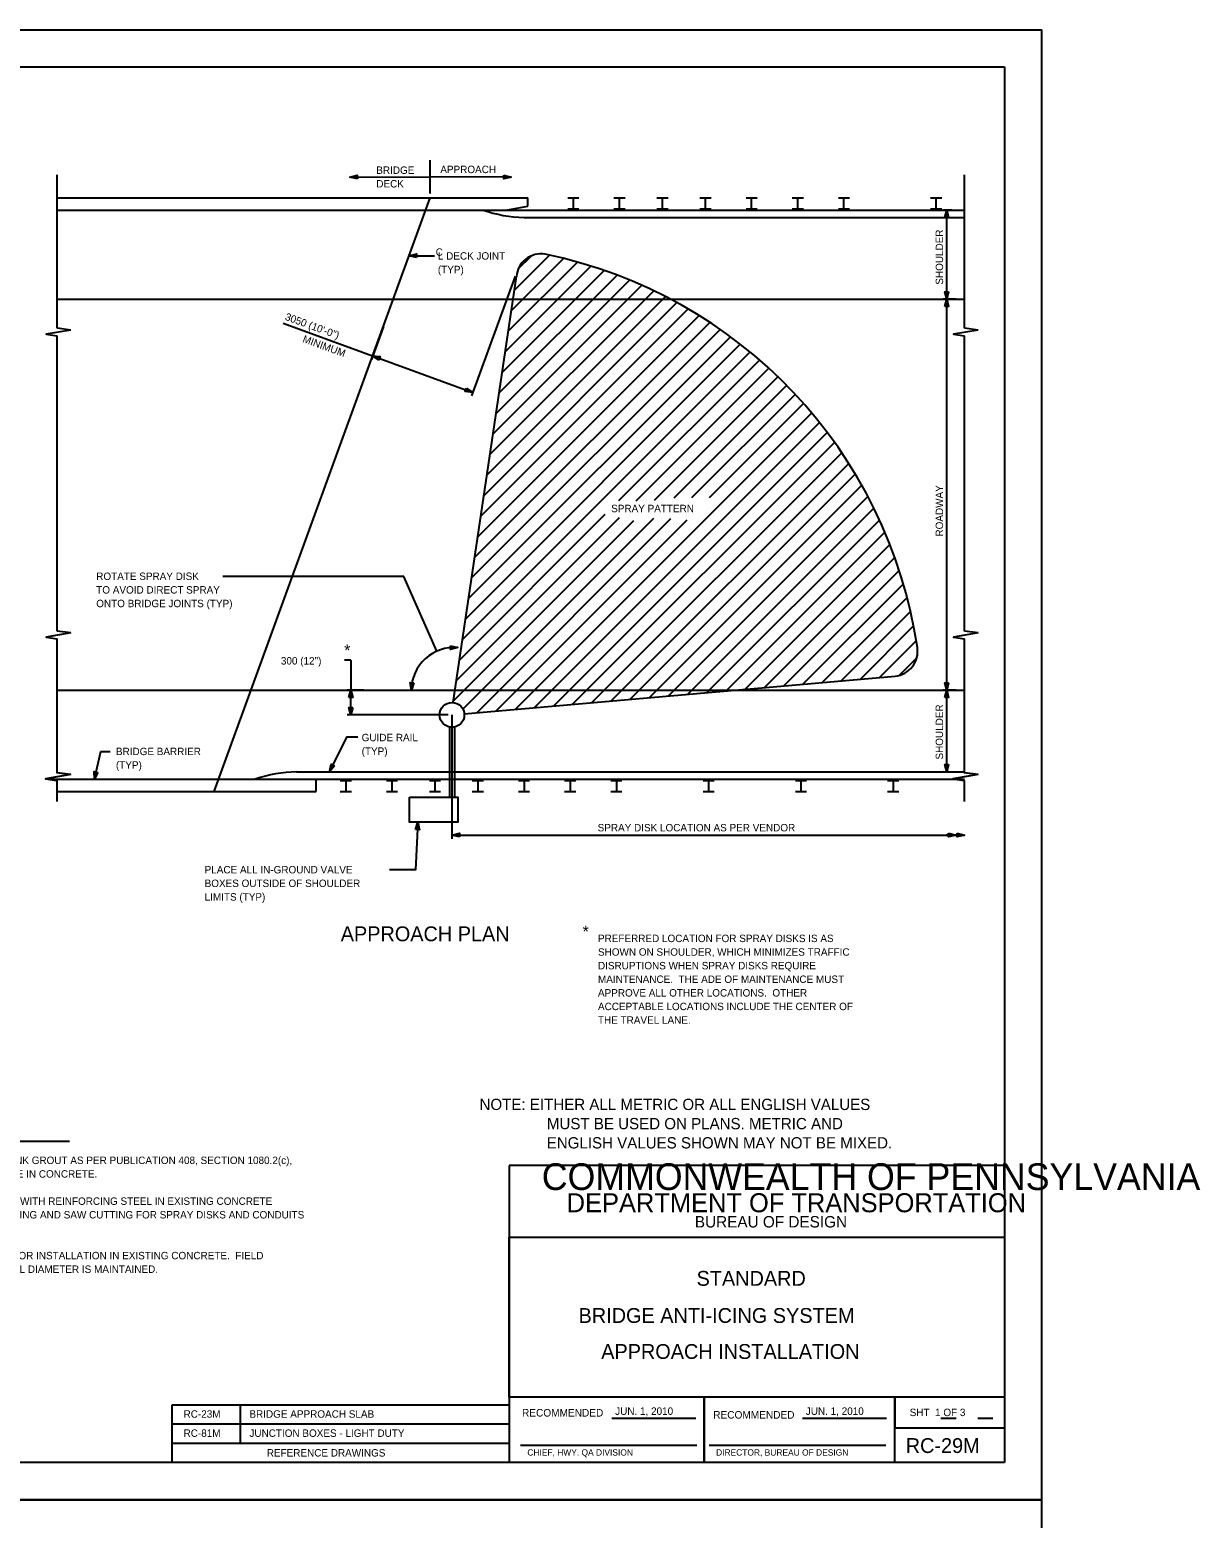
# Model space of a CAD drawing. Extents: x 3239 to 4230, y -4276 to -2494.
# Drawn here: x 3671 to 4144, y -3096 to -2494 of the extents above; entities that cross this region are included whole.
import ezdxf

# ---------------------------------------------------------------- set-up
doc = ezdxf.new("R2010")
doc.units = 0
for name, color, linetype in [('1', 7, 'Continuous'), ('2', 7, 'Continuous'), ('40', 7, 'Continuous'), ('PLT-BNDY', 7, 'Continuous')]:
    doc.layers.add(name, color=color, linetype=linetype)

msp = doc.modelspace()

# ---------------------------------------------------------------- linework, layer by layer
at = {"layer": '1'}
for p, q in [((4065.03, -2953.29), (3865.03, -2953.29)), ((3865.03, -2953.29), (3865.03, -3073.29)), ((3865.03, -3046.93), (3865.03, -2982.25)), ((3865.03, -2982.25), (4065.03, -2982.25)), ((4065.03, -3046.93), (3865.03, -3046.93)), ((3943.83, -3073.29), (3943.83, -3046.93)), ((3943.83, -3046.93), (3943.83, -3073.29)), ((4020.83, -3073.29), (4020.83, -3046.93)), ((4020.83, -3046.93), (4020.83, -3059.25)), ((3906.49, -3055.3), (3940.38, -3055.3)), ((3983.49, -3055.3), (4017.36, -3055.3)), ((4039.41, -3055.33), (4045.55, -3055.33)), ((4054.27, -3055.33), (4060.43, -3055.33)), ((4020.83, -3059.25), (4065.03, -3059.25)), ((3869.59, -3066.21), (3940.84, -3066.21)), ((3945.76, -3066.21), (4017.1, -3066.21))]:
    msp.add_line(p, q, dxfattribs=at)
at = {"layer": '2'}
for p, q in [((3279.03, -2509.29), (4065.03, -2509.29)), ((4065.03, -2509.29), (4065.03, -3073.29)), ((3833.14, -2560.5), (3833.14, -2547.02)), ((3682.42, -2614.94), (3682.42, -2552.89)), ((3800.66, -2553.82), (3833.14, -2553.71)), ((3865.82, -2553.82), (3833.14, -2553.71)), ((4048.93, -2614.94), (4048.93, -2552.89)), ((3682.42, -2562.14), (3872.54, -2562.14)), ((3745.78, -2802.15), (3833.14, -2562.14)), ((3872.54, -2565.54), (3872.54, -2562.14)), ((3888.7, -2562.15), (3893.2, -2562.15)), ((3890.95, -2566.65), (3890.95, -2562.15)), ((3907.34, -2562.15), (3911.84, -2562.15)), ((3909.59, -2566.65), (3909.59, -2562.15)), ((3924.7, -2562.15), (3929.2, -2562.15)), ((3926.95, -2566.65), (3926.95, -2562.15)), ((3942.06, -2562.15), (3946.56, -2562.15)), ((3944.31, -2566.65), (3944.31, -2562.15)), ((3960.7, -2562.15), (3965.2, -2562.15)), ((3962.95, -2566.65), (3962.95, -2562.15)), ((3979.34, -2562.15), (3983.84, -2562.15)), ((3981.59, -2566.65), (3981.59, -2562.15)), ((3997.98, -2562.15), (4002.48, -2562.15)), ((4000.23, -2566.65), (4000.23, -2562.15)), ((4035.26, -2562.15), (4039.76, -2562.15)), ((4037.51, -2566.65), (4037.51, -2562.15)), ((3682.42, -2567.14), (3863.67, -2567.14)), ((3863.67, -2567.14), (3872.54, -2565.54)), ((3863.67, -2567.14), (4048.93, -2567.14)), ((3888.7, -2566.65), (3893.2, -2566.65)), ((3907.34, -2566.65), (3911.84, -2566.65)), ((3924.7, -2566.65), (3929.2, -2566.65)), ((3942.06, -2566.65), (3946.56, -2566.65)), ((3960.7, -2566.65), (3965.2, -2566.65)), ((3979.34, -2566.65), (3983.84, -2566.65)), ((3997.98, -2566.65), (4002.48, -2566.65)), ((4035.26, -2566.65), (4039.76, -2566.65)), ((4043.79, -2567.14), (4040.28, -2567.14)), ((4041.78, -2603.14), (4041.78, -2567.14)), ((3871.04, -2570.14), (4048.93, -2570.14)), ((3824.59, -2585.63), (3834.84, -2585.63)), ((3867.1, -2599.52), (3881.26, -2585.36)), ((3868.83, -2590.71), (3873.82, -2585.72)), ((3862.16, -2632.74), (3903.37, -2591.53)), ((3863.39, -2624.43), (3898.03, -2589.8)), ((3864.63, -2616.13), (3892.59, -2588.16)), ((3865.86, -2607.82), (3886.99, -2586.7)), ((3842.32, -2766.17), (3867.92, -2593.97)), ((3867.46, -2593.9), (3849.79, -2642.25)), ((3858.45, -2657.66), (3918.6, -2597.51)), ((3859.69, -2649.35), (3913.62, -2595.42)), ((3860.92, -2641.05), (3908.56, -2593.41)), ((3682.42, -2603.14), (4048.93, -2603.14)), ((3855.98, -2674.27), (3928.15, -2602.1)), ((3857.22, -2665.96), (3923.41, -2599.77)), ((4045.53, -2603.14), (4040.28, -2603.14)), ((4041.78, -2761.15), (4041.78, -2603.14)), ((3852.28, -2699.19), (3941.73, -2609.74)), ((3853.51, -2690.88), (3937.28, -2607.11)), ((3854.75, -2682.58), (3932.78, -2604.54)), ((3687.93, -2615.62), (3682.42, -2614.94)), ((3773.68, -2612.84), (3850.3, -2640.84)), ((3814.17, -2614.24), (3809.34, -2627.47)), ((3849.81, -2715.8), (3950.24, -2615.37)), ((3851.04, -2707.49), (3946.01, -2612.52)), ((4054.44, -2615.62), (4048.93, -2614.94)), ((3682.42, -2737.37), (3682.42, -2617.96)), ((3847.34, -2732.41), (3958.37, -2621.38)), ((3848.57, -2724.11), (3954.35, -2618.32)), ((4048.93, -2737.37), (4048.93, -2617.96)), ((3846.1, -2740.72), (3962.32, -2624.5)), ((3909.32, -2684.57), (3966.13, -2627.76)), ((3916.26, -2684.7), (3969.89, -2631.07)), ((3923.66, -2684.38), (3973.52, -2634.51)), ((3931.65, -2683.46), (3977.08, -2638.02)), ((3938.85, -2683.33), (3980.55, -2641.63)), ((3945.99, -2683.26), (3983.9, -2645.34)), ((3867.4, -2768.91), (3987.21, -2649.11)), ((3875.15, -2768.24), (3990.36, -2653.03)), ((3882.9, -2767.56), (3993.47, -2656.99)), ((3890.65, -2766.88), (3996.44, -2661.09)), ((3898.4, -2766.2), (3999.34, -2665.26)), ((3906.15, -2765.52), (4002.15, -2669.52)), ((3913.9, -2764.85), (4004.83, -2673.91)), ((3921.65, -2764.17), (4007.46, -2678.36)), ((3929.4, -2763.49), (4009.92, -2682.96)), ((3937.15, -2762.81), (4012.32, -2687.64)), ((3842.4, -2765.64), (3915.4, -2692.63)), ((3843.63, -2757.33), (3909.58, -2691.39)), ((3844.87, -2749.02), (3903.81, -2690.08)), ((3846.26, -2768.84), (3923.46, -2691.65)), ((3851.91, -2770.27), (3930.33, -2691.84)), ((3859.65, -2769.59), (3936.95, -2692.3)), ((3944.89, -2762.13), (4014.6, -2692.43)), ((3952.64, -2761.46), (4016.75, -2697.35)), ((3960.39, -2760.78), (4018.82, -2702.35)), ((3968.14, -2760.1), (4020.73, -2707.51)), ((3822.44, -2715.2), (3749.29, -2715.2)), ((3835.78, -2745.36), (3822.44, -2715.2)), ((3975.89, -2759.42), (4022.53, -2712.78)), ((3983.64, -2758.74), (4024.23, -2718.15)), ((3991.39, -2758.07), (4025.73, -2723.72)), ((3999.14, -2757.39), (4027.12, -2729.4)), ((4006.89, -2756.71), (4028.39, -2735.2)), ((3687.93, -2738.05), (3682.42, -2737.37)), ((3682.42, -2794.58), (3682.42, -2740.39)), ((4014.64, -2756.03), (4029.43, -2741.23)), ((4054.44, -2738.05), (4048.93, -2737.37)), ((4048.93, -2794.58), (4048.93, -2740.39)), ((4022.57, -2755.17), (4029.67, -2748.07)), ((3801.05, -2749.05), (3798.47, -2749.05)), ((3801.05, -2749.05), (3801.05, -2761.15)), ((3801.05, -2771.15), (3801.05, -2760.8)), ((3846.86, -2770.71), (4020.9, -2755.49)), ((3682.42, -2761.15), (4048.93, -2761.15)), ((3806.29, -2761.15), (3799.55, -2761.15)), ((4045.55, -2761.15), (4040.28, -2761.15)), ((4041.78, -2794.15), (4041.78, -2761.15)), ((3840.38, -2771.15), (3799.55, -2771.15)), ((3841.88, -2771.15), (3841.88, -2821.23)), ((3840.88, -2776.05), (3840.88, -2804.44)), ((3842.88, -2776.05), (3842.88, -2804.44)), ((3687.62, -2795.26), (3682.11, -2794.58)), ((3687.93, -2795.26), (3682.42, -2794.58)), ((3779.09, -2794.15), (4048.93, -2794.15)), ((4040.43, -2794.15), (4040.28, -2794.15)), ((4054.13, -2795.26), (4048.62, -2794.58)), ((4054.44, -2795.26), (4048.93, -2794.58)), ((3679.34, -2797.15), (4048.93, -2797.15)), ((3682.42, -2806.14), (3682.42, -2797.6)), ((3682.42, -2802.15), (3787.01, -2802.15)), ((3787.01, -2802.15), (3787.01, -2797.15)), ((3796.76, -2797.63), (3801.26, -2797.63)), ((3796.76, -2802.13), (3801.26, -2802.13)), ((3799.01, -2797.63), (3799.01, -2802.13)), ((3815.4, -2797.63), (3819.9, -2797.63)), ((3815.4, -2802.13), (3819.9, -2802.13)), ((3817.65, -2797.63), (3817.65, -2802.13)), ((3832.76, -2797.63), (3837.26, -2797.63)), ((3832.76, -2802.13), (3837.26, -2802.13)), ((3835.01, -2797.63), (3835.01, -2802.13)), ((3850.11, -2797.63), (3854.61, -2797.63)), ((3850.11, -2802.13), (3854.61, -2802.13)), ((3852.36, -2797.63), (3852.36, -2802.13)), ((3868.76, -2797.63), (3873.26, -2797.63)), ((3868.76, -2802.13), (3873.26, -2802.13)), ((3871.01, -2797.63), (3871.01, -2802.13)), ((3887.4, -2797.63), (3891.9, -2797.63)), ((3887.4, -2802.13), (3891.9, -2802.13)), ((3889.65, -2797.63), (3889.65, -2802.13)), ((3906.04, -2797.63), (3910.54, -2797.63)), ((3906.04, -2802.13), (3910.54, -2802.13)), ((3908.29, -2797.63), (3908.29, -2802.13)), ((3943.32, -2797.63), (3947.82, -2797.63)), ((3943.32, -2802.13), (3947.82, -2802.13)), ((3945.57, -2797.63), (3945.57, -2802.13)), ((3980.6, -2797.63), (3985.1, -2797.63)), ((3980.6, -2802.13), (3985.1, -2802.13)), ((3982.85, -2797.63), (3982.85, -2802.13)), ((4017.88, -2797.63), (4022.38, -2797.63)), ((4017.88, -2802.13), (4022.38, -2802.13)), ((4020.13, -2797.63), (4020.13, -2802.13)), ((4048.93, -2806.14), (4048.93, -2797.6)), ((3841.88, -2819.73), (4048.93, -2819.73)), ((4045.53, -2819.73), (4041.51, -2819.73)), ((4048.93, -2821.23), (4048.93, -2821.23)), ((3583.23, -2943.37), (3687.39, -2943.37)), ((3728.73, -3050.08), (3728.73, -3073.29)), ((3865.03, -3050.08), (3728.73, -3050.08)), ((3756.39, -3050.08), (3756.39, -3065.55)), ((3865.03, -3057.82), (3728.73, -3057.82)), ((3865.03, -3065.55), (3728.73, -3065.55)), ((4065.03, -3073.29), (3279.03, -3073.29)), ((4080.03, -3088.29), (4080.03, -3088.29))]:
    msp.add_line(p, q, dxfattribs=at)
for points in [[(3803.67, -2554.56), (3800.66, -2553.82), (3803.66, -2553.06)], [(3862.82, -2553.06), (3865.82, -2553.82), (3862.82, -2554.56)], [(4041.03, -2570.14), (4041.78, -2567.14), (4042.53, -2570.14)], [(3827.59, -2586.38), (3824.59, -2585.63), (3827.59, -2584.88)], [(4042.53, -2600.14), (4041.78, -2603.14), (4041.03, -2600.14)], [(4041.03, -2606.14), (4041.78, -2603.14), (4042.53, -2606.14)], [(3812.41, -2627.79), (3809.85, -2626.06), (3812.93, -2626.39)], [(3847.74, -2639.11), (3850.3, -2640.84), (3847.23, -2640.52)], [(3841.26, -2743.21), (3844.26, -2743.96), (3841.26, -2744.71)], [(3826.51, -2758.22), (3825.5, -2761.15), (3825.02, -2758.09)], [(4042.53, -2758.15), (4041.78, -2761.15), (4041.03, -2758.15)], [(3800.3, -2764.15), (3801.05, -2761.15), (3801.8, -2764.15)], [(4041.03, -2764.15), (4041.78, -2761.15), (4042.53, -2764.15)], [(3801.8, -2768.15), (3801.05, -2771.15), (3800.3, -2768.15)], [(3698.88, -2794.39), (3697.47, -2797.15), (3697.42, -2794.06)], [(3794.49, -2791.8), (3792.47, -2794.15), (3793.15, -2791.13)], [(4042.53, -2791.15), (4041.78, -2794.15), (4041.03, -2791.15)], [(3824.68, -2804.44), (3844.3, -2804.44), (3844.3, -2814.57), (3824.68, -2814.57)], [(3827.22, -2817.53), (3828.11, -2814.57), (3828.72, -2817.6)], [(3844.88, -2820.48), (3841.88, -2819.73), (3844.88, -2818.98)], [(4042.53, -2818.98), (4045.53, -2819.73), (4042.53, -2820.48)], [(4045.93, -2818.98), (4048.93, -2819.73), (4045.93, -2820.48)]]:
    msp.add_lwpolyline(points, close=True, dxfattribs=at)
for points in [[(3687.93, -2615.62), (3678.03, -2617.32), (3682.42, -2617.96)], [(4054.44, -2615.62), (4044.54, -2617.32), (4048.93, -2617.96)], [(3687.93, -2738.05), (3678.03, -2739.74), (3682.42, -2740.39)], [(4054.44, -2738.05), (4044.54, -2739.74), (4048.93, -2740.39)], [(3792.47, -2794.15), (3799.54, -2780.04), (3803.9, -2780.04)], [(3697.47, -2797.15), (3700.07, -2785.9), (3703.88, -2785.9)], [(3687.62, -2795.26), (3677.72, -2796.96), (3682.11, -2797.6)], [(3687.93, -2795.26), (3678.03, -2796.96), (3682.42, -2797.6)], [(4054.13, -2795.26), (4044.23, -2796.96), (4048.62, -2797.6)], [(4054.44, -2795.26), (4044.54, -2796.96), (4048.93, -2797.6)], [(3828.11, -2814.57), (3827.21, -2833.73), (3819.62, -2833.73), (3816.71, -2833.73)]]:
    msp.add_lwpolyline(points, dxfattribs=at)
msp.add_circle((3841.88, -2771.15), 5, dxfattribs=at)
msp.add_circle((3841.88, -2771.15), 5, dxfattribs=at)
for centre, radius, start, end in [((3872.35, -2515.2), 54.95, 250.93027, 268.63888), ((3877.88, -2594.84), 10, 80.66099, 175), ((3841.17, -2771.86), 190.78, 8.42806, 78.4074), ((3842.76, -2761.15), 17.25, 85, 180), ((4020.02, -2745.52), 10, 275, 9.33901), ((3780.4, -2849.08), 54.95, 91.36112, 109.06973)]:
    msp.add_arc(centre, radius, start, end, dxfattribs=at)
at = {"layer": 'PLT-BNDY'}
for points in [[(3239.03, -2494.29), (4080.03, -2494.29), (4080.03, -3088.29), (3239.03, -3088.29)], [(3239.03, -3088.29), (4080.03, -3088.29), (4080.03, -3682.29), (3239.03, -3682.29)]]:
    msp.add_lwpolyline(points, close=True, dxfattribs=at)

# ---------------------------------------------------------------- texts
at = {"layer": '1'}
for s, height, p in [('COMMONWEALTH OF PENNSYLVANIA', 10.7834, (3878.18, -2963.15)), ('DEPARTMENT OF TRANSPORTATION', 7.6843, (3888.24, -2972.14)), ('BUREAU OF DESIGN', 4.6221, (3940.01, -2978.3)), ('RECOMMENDED', 3.048, (3870.19, -3054.7)), ('JUN. 1, 2010', 3, (3907.83, -3054.01)), ('APPROVED', 0.0192, (3908.05, -3055.36)), ('RECOMMENDED', 3.048, (3947.43, -3055.53)), ('JUN. 1, 2010', 3, (3984.83, -3054.01)), ('CHIEF, HWY. QA DIVISION', 2.54, (3872.34, -3070.47)), ('DIRECTOR, BUREAU OF DESIGN', 2.54, (3948.59, -3070.47))]:
    msp.add_text(s, height=height, dxfattribs=at).set_placement(p)
at = {"layer": '2'}
for s, height, p in [('BRIDGE', 3, (3811.33, -2552.52)), ('APPROACH', 3, (3837.18, -2552.22)), ('DECK', 3, (3811.33, -2558.02)), ('C', 3, (3835.32, -2585.63)), ('L DECK JOINT', 3, (3836.2, -2587.18)), ('(TYP)', 3, (3836.2, -2592.68)), ('SPRAY PATTERN', 3, (3906.21, -2689.24)), ('ROTATE SPRAY DISK', 3, (3698.2, -2716.63)), ('TO AVOID DIRECT SPRAY', 3, (3698.2, -2722.13)), ('ONTO BRIDGE JOINTS (TYP)', 3, (3698.2, -2727.63)), ('*', 4.8, (3798.36, -2747.45)), ('300 (12")', 3, (3772.79, -2750.8)), ('GUIDE RAIL', 3, (3805.41, -2781.8)), ('BRIDGE BARRIER', 3, (3706.15, -2787.42)), ('(TYP)', 3, (3805.41, -2787.3)), ('(TYP)', 3, (3706.15, -2792.92)), ('SPRAY DISK LOCATION AS PER VENDOR', 3, (3900.74, -2818.23)), ('PLACE ALL IN-GROUND VALVE', 3, (3741.99, -2835.21)), ('BOXES OUTSIDE OF SHOULDER ', 3, (3741.99, -2840.71)), ('LIMITS (TYP)', 3, (3741.99, -2846.21)), ('APPROACH PLAN', 6, (3796.96, -2862.62)), ('*', 4.8, (3894.67, -2861.1)), ('PREFERRED LOCATION FOR SPRAY DISKS IS AS', 3, (3900.88, -2862.97)), ('SHOWN ON SHOULDER, WHICH MINIMIZES TRAFFIC', 3, (3900.88, -2868.47)), ('DISRUPTIONS WHEN SPRAY DISKS REQUIRE', 3, (3900.88, -2873.97)), ('MAINTENANCE.  THE ADE OF MAINTENANCE MUST', 3, (3900.88, -2879.47)), ('APPROVE ALL OTHER LOCATIONS.  OTHER', 3, (3900.88, -2884.97)), ('ACCEPTABLE LOCATIONS INCLUDE THE CENTER OF', 3, (3900.88, -2890.47)), ('THE TRAVEL LANE.', 3, (3900.88, -2895.97)), (' 7. USE A PREMIXED FLOWABLE NONSHRINK GROUT AS PER PUBLICATION 408, SECTION 1080.2(c),  ', 3, (3583.19, -2952.65)), ('    FOR EMBEDDING ANTI-ICING HARDWARE IN CONCRETE.', 3, (3583.19, -2958.15)), (' 8. TO AVOID DAMAGING OR CONFLICTING WITH REINFORCING STEEL IN EXISTING CONCRETE ', 3, (3583.19, -2969.15)), ('    APPROACH SLABS, LIMIT MAXIMUM CORING AND SAW CUTTING FOR SPRAY DISKS AND CONDUITS', 3, (3583.19, -2974.65)), (' 9. NO CONDUIT JOINTS ARE PERMITTED FOR INSTALLATION IN EXISTING CONCRETE.  FIELD', 3, (3583.19, -2991.15)), ('    BENDS ARE PERMITTED WHEN INTERNAL DIAMETER IS MAINTAINED.', 3, (3583.19, -2996.65)), ('STANDARD', 6, (3940.7, -3001.86)), ('BRIDGE ANTI-ICING SYSTEM', 6, (3893.04, -3016.86)), ('APPROACH INSTALLATION', 6, (3902.18, -3031.41)), ('RC-23M', 3, (3733.48, -3055.17)), ('BRIDGE APPROACH SLAB', 3, (3760.08, -3055.17)), ('SHT  1 OF 3', 3, (4026.79, -3054.52)), ('RC-81M', 3, (3733.48, -3062.9)), ('JUNCTION BOXES - LIGHT DUTY', 3, (3760.08, -3062.9)), ('RC-29M', 6, (4025.19, -3069.43)), ('REFERENCE DRAWINGS', 3, (3767.09, -3070.86))]:
    msp.add_text(s, height=height, dxfattribs=at).set_placement(p)
for s, rotation, p in [('SHOULDER', 90, (4040.28, -2597.3)), ('3050 (10\'-0")', 339.92461, (3774.2, -2611.43)), ('MINIMUM', 339.92469, (3781.29, -2620.41)), ('ROADWAY', 90, (4040.28, -2699.08)), ('SHOULDER', 90, (4040.28, -2789.2))]:
    msp.add_text(s, height=3, rotation=rotation, dxfattribs=at).set_placement(p)
at = {"layer": '40'}
for s, p in [('NOTE: EITHER ALL METRIC OR ALL ENGLISH VALUES', (3853.02, -2930.83)), ('MUST BE USED ON PLANS. METRIC AND', (3880.24, -2938.6)), ('ENGLISH VALUES SHOWN MAY NOT BE MIXED.', (3880.17, -2946.36))]:
    msp.add_text(s, height=4.5587, dxfattribs=at).set_placement(p)

doc.saveas('drawing.dxf')
